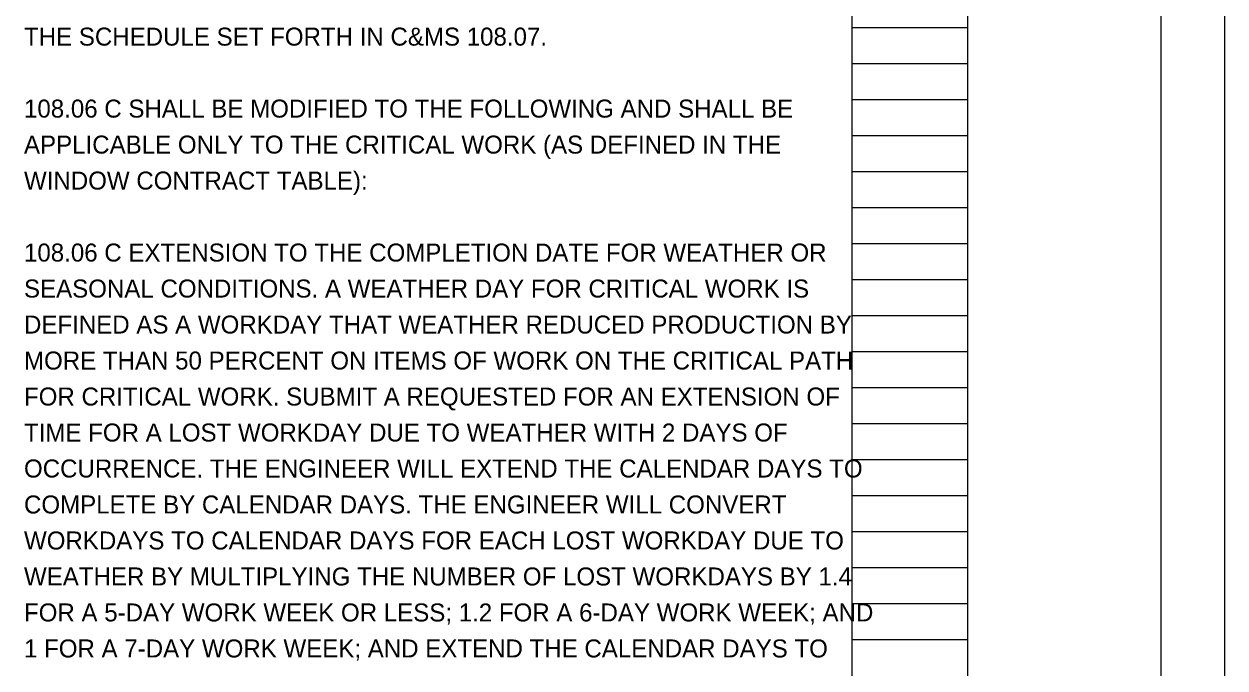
# Model space of a CAD drawing. Extents: x -1.3 to 43.7, y -2.4 to 22.
# Drawn here: x 24.66 to 34, y 5.24 to 10.25 of the extents above; entities that cross this region are included whole.
import ezdxf

# ---------------------------------------------------------------- set-up
doc = ezdxf.new("R2010")
doc.units = 0
for name, color, linetype in [('SH_Border', 7, 'Continuous'), ('SH_Cut_Line', 7, 'Continuous'), ('SH_Data', 7, 'Continuous'), ('SH_Text', 7, 'Continuous')]:
    doc.layers.add(name, color=color, linetype=linetype)

msp = doc.modelspace()

# ---------------------------------------------------------------- linework, layer by layer
at = {"layer": 'SH_Border'}
msp.add_line((32, 0.5), (32, 21.5), dxfattribs=at)
msp.add_lwpolyline([(1.5, 21.5), (33.5, 21.5), (33.5, 0.5), (1.5, 0.5)], close=True, dxfattribs=at)
at = {"layer": 'SH_Cut_Line'}
msp.add_lwpolyline([(0, 0), (34, 0), (34, 22), (0, 22)], close=True, dxfattribs=at)
at = {"layer": 'SH_Data'}
for p, q in [((31.1, 0.98), (31.1, 21.14)), ((32, 0.98), (32, 21.14)), ((31.1, 10.22), (32, 10.22)), ((31.1, 9.94), (32, 9.94)), ((31.1, 9.66), (32, 9.66)), ((31.1, 9.38), (32, 9.38)), ((31.1, 9.1), (32, 9.1)), ((31.1, 8.82), (32, 8.82)), ((31.1, 8.54), (32, 8.54)), ((31.1, 8.26), (32, 8.26)), ((31.1, 7.98), (32, 7.98)), ((31.1, 7.7), (32, 7.7)), ((31.1, 7.42), (32, 7.42)), ((31.1, 7.14), (32, 7.14)), ((31.1, 6.86), (32, 6.86)), ((31.1, 6.58), (32, 6.58)), ((31.1, 6.3), (32, 6.3)), ((31.1, 6.02), (32, 6.02)), ((31.1, 5.74), (32, 5.74)), ((31.1, 5.46), (32, 5.46))]:
    msp.add_line(p, q, dxfattribs=at)

# ---------------------------------------------------------------- texts
at = {"layer": 'SH_Text'}
for s, p in [('THE SCHEDULE SET FORTH IN C&MS 108.07.', (24.66, 10.08)), ('108.06 C SHALL BE MODIFIED TO THE FOLLOWING AND SHALL BE ', (24.66, 9.52)), ('APPLICABLE ONLY TO THE CRITICAL WORK (AS DEFINED IN THE ', (24.66, 9.24)), ('WINDOW CONTRACT TABLE):', (24.66, 8.96)), ('108.06 C EXTENSION TO THE COMPLETION DATE FOR WEATHER OR ', (24.66, 8.4)), ('SEASONAL CONDITIONS. A WEATHER DAY FOR CRITICAL WORK IS ', (24.66, 8.12)), ('DEFINED AS A WORKDAY THAT WEATHER REDUCED PRODUCTION BY ', (24.66, 7.84)), ('MORE THAN 50 PERCENT ON ITEMS OF WORK ON THE CRITICAL PATH ', (24.66, 7.56)), ('FOR CRITICAL WORK. SUBMIT A REQUESTED FOR AN EXTENSION OF ', (24.66, 7.28)), ('TIME FOR A LOST WORKDAY DUE TO WEATHER WITH 2 DAYS OF ', (24.66, 7)), ('OCCURRENCE. THE ENGINEER WILL EXTEND THE CALENDAR DAYS TO ', (24.66, 6.72)), ('COMPLETE BY CALENDAR DAYS. THE ENGINEER WILL CONVERT ', (24.66, 6.44)), ('WORKDAYS TO CALENDAR DAYS FOR EACH LOST WORKDAY DUE TO ', (24.66, 6.16)), ('WEATHER BY MULTIPLYING THE NUMBER OF LOST WORKDAYS BY 1.4 ', (24.66, 5.88)), ('FOR A 5-DAY WORK WEEK OR LESS; 1.2 FOR A 6-DAY WORK WEEK; AND ', (24.66, 5.6)), ('1 FOR A 7-DAY WORK WEEK; AND EXTEND THE CALENDAR DAYS TO ', (24.66, 5.32))]:
    msp.add_text(s, height=0.14, dxfattribs=at).set_placement(p)

doc.saveas('drawing.dxf')
